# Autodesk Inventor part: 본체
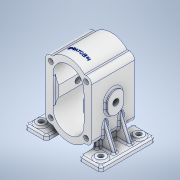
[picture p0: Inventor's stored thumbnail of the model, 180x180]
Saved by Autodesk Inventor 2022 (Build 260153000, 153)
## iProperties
Created: 2023-06
Part Number: 본체
Material: 알루미늄 6061
Document SubType Name: Modeling
Designer: PC-11
Density: 2.7 g/cm^3
Appearance: 알루미늄 - 평지
Author: PC-11
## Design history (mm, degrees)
sketch "스케치1"
  geometry: L1 (-42.5, 55)-(42.5, 55); L2 (42.5, 55)-(42.5, -55); L3 (42.5, -55)-(-42.5, -55); L4 (-42.5, -55)-(-42.5, 55); L5 (-42.5, 55)-(42.5, -55); L6 (42.5, 55)-(-42.5, -55); L7 (0, 0)-(0, -27.5); L8 (0, 0)-(0, 27.5); C1 r 40 at (0, -27.5); C2 r 40 at (0, 27.5); 4 further points
  constraints: 16 end point, 2 centre point, 2 coincident, 2 midpoint, 2 parallel, 2 vertical, 1 horizontal, 1 perpendicular
  dimensions: "d0" = 85 distance of L2.end L3.end; "d1" = 110 distance of L1.end L2.end; "d2" = 27.5 distance of L7.start L7.end; "d3" = 80 diameter of C1; "d4" = 27.5 distance of L7.start L8.end; "d5" = 80 diameter of C2
extrude "돌출1" new body sketch "스케치1" stored distance "d6" = 79; taper "d7" = 0 deg
fillet "모깎기1" dims "d8" = 10
sketch "스케치3"
  geometry: L1 (-32.5, -55)-(-29.047, -55) reference; L2 (29.047, -55)-(32.5, -55) reference; L3 (42.5, -45)-(42.5, 45) reference; L4 (32.5, 55)-(29.047, 55) reference; L5 (-29.047, 55)-(-32.5, 55) reference; L6 (-42.5, 45)-(-42.5, -45) reference; L7 (-22.5, 27.5)-(22.5, 27.5); L8 (22.5, 27.5)-(22.5, -27.5); L9 (22.5, -27.5)-(-22.5, -27.5); L10 (-22.5, -27.5)-(-22.5, 27.5); L11 (-22.5, 27.5)-(22.5, -27.5); L12 (22.5, 27.5)-(-22.5, -27.5); C1 r 28.5 at (0, -27.5); C2 r 28.5 at (0, 27.5); A1 r 10 centre (-32.5, -45) between (-42.5, -45) and (-32.5, -55) reference; A2 r 40 centre (0, -27.5) between (-29.047, -55) and (29.047, -55) reference; A3 r 10 centre (32.5, -45) between (32.5, -55) and (42.5, -45) reference; A4 r 10 centre (32.5, 45) between (42.5, 45) and (32.5, 55) reference; A5 r 40 centre (0, 27.5) between (29.047, 55) and (-29.047, 55) reference; A6 r 10 centre (-32.5, 45) between (-32.5, 55) and (-42.5, 45) reference; 7 further points
  constraints: 12 end point, 4 midpoint, 2 centre point, 2 coincident, 2 parallel, 1 horizontal, 1 perpendicular, 1 tangent, 1 vertical alignment
  dimensions: "d11" = 45 distance of L8.end L9.end; "d12" = 57 diameter of C1; "d13" = 57 diameter of C2
extrude "돌출2" cut sketch "스케치3" distance "d14" = 79; taper "d15" = 0 deg
sketch "스케치4"
  geometry: L1 (-22.5, -10.007)-(-22.5, 10.007) reference; L2 (22.5, 10.007)-(22.5, -10.007) reference; L3 (-32.5, -55)-(-29.047, -55) reference; L4 (29.047, -55)-(32.5, -55) reference; L5 (42.5, -45)-(42.5, 45) reference; L6 (32.5, 55)-(29.047, 55) reference; L7 (-29.047, 55)-(-32.5, 55) reference; L8 (-42.5, 45)-(-42.5, -45) reference; L9 (-28.5, 24)-(28.5, 24); L10 (28.5, 24)-(28.5, -24); L11 (28.5, -24)-(-28.5, -24); L12 (-28.5, -24)-(-28.5, 24); L13 (-28.5, 24)-(28.5, -24); L14 (28.5, 24)-(-28.5, -24); A1 r 28.5 centre (0, -27.5) between (-22.5, -10.007) and (22.5, -10.007) reference; A2 r 28.5 centre (0, 27.5) between (22.5, 10.007) and (-22.5, 10.007) reference; A3 r 10 centre (-32.5, -45) between (-42.5, -45) and (-32.5, -55) reference; A4 r 40 centre (0, -27.5) between (-29.047, -55) and (29.047, -55) reference; A5 r 10 centre (32.5, -45) between (32.5, -55) and (42.5, -45) reference; A6 r 10 centre (32.5, 45) between (42.5, 45) and (32.5, 55) reference; A7 r 40 centre (0, 27.5) between (29.047, 55) and (-29.047, 55) reference; A8 r 10 centre (-32.5, 45) between (-32.5, 55) and (-42.5, 45) reference; 5 further points
  constraints: 12 end point, 2 midpoint, 2 parallel, 1 horizontal, 1 perpendicular
  dimensions: "d16" = 57 distance of L10.end L11.end; "d17" = 48 distance of L9.end L10.end
extrude "돌출3" cut sketch "스케치4" distance "d18" = 4.5; taper "d19" = 0 deg
node "작업 평면2"
  node "작업 평면1"
sketch "스케치6"
  geometry: L1 (-30, -50)-(-70, -50); L2 (-70, -50)-(-70, 50); L3 (-70, 50)-(-30, 50); L4 (-30, 50)-(-30, -50); L5 (-42.5, 39.5)-(-42.5, -39.5) reference; L6 (0, 0)-(0, -39.5); L7 (-29.047, -39.5)-(29.047, -39.5) reference; L8 (70, 50)-(30, 50); L9 (70, -50)-(70, 50); L10 (30, 50)-(30, -50); L11 (30, -50)-(70, -50); 2 further points
  constraints: 18 end point, 4 symmetric about line, 3 midpoint, 2 parallel, 1 horizontal, 1 horizontal alignment, 1 perpendicular
  dimensions: "d21" = 40 distance of L2.end L3.end; "d22" = 100 distance of L1.end L2.end; "d23" = 70 distance from line of L2 L6.start
extrude "돌출4" join sketch "스케치6" distance "d24" = 9; taper "d25" = 0 deg
node "작업 평면3"
node "작업 평면4"
sketch "스케치7"
  geometry: L1 (22.5, -10.007)-(22.5, 10.007) reference; L2 (-22.5, 10.007)-(-22.5, -10.007) reference; L3 (-32.5, 55)-(-29.047, 55) reference; L4 (29.047, 55)-(32.5, 55) reference; L5 (42.5, 45)-(42.5, -45) reference; L6 (32.5, -55)-(29.047, -55) reference; L7 (-29.047, -55)-(-32.5, -55) reference; L8 (-42.5, -45)-(-42.5, 45) reference; L9 (30, -76.5)-(30, -67.5) reference; L10 (30, -67.5)-(70, -67.5) reference; L11 (70, -67.5)-(70, -76.5) reference; L12 (70, -76.5)-(30, -76.5) reference; L13 (-30, -67.5)-(-30, -76.5) reference; L14 (-30, -76.5)-(-70, -76.5) reference; L15 (-70, -76.5)-(-70, -67.5) reference; L16 (-70, -67.5)-(-30, -67.5) reference; L17 (70, -67.5)-(30, -67.5) reference; L18 (62, -67.5)-(42.5, -21.561); L19 (42.5, 45)-(42.5, -45) reference; L20 (62, -67.5)-(30, -67.5); L21 (30, -67.5)-(30, -55); L22 (32.5, -55)-(29.047, -55) reference; A1 r 28.5 centre (0, 27.5) between (22.5, 10.007) and (-22.5, 10.007) reference; A2 r 28.5 centre (0, -27.5) between (-22.5, -10.007) and (22.5, -10.007) reference; A3 r 10 centre (-32.5, 45) between (-32.5, 55) and (-42.5, 45) reference; A4 r 40 centre (0, 27.5) between (29.047, 55) and (-29.047, 55) reference; A5 r 10 centre (32.5, 45) between (42.5, 45) and (32.5, 55) reference; A6 r 10 centre (32.5, -45) between (32.5, -55) and (42.5, -45) reference; A7 r 40 centre (0, -27.5) between (-29.047, -55) and (29.047, -55) reference; A8 r 10 centre (-32.5, -45) between (-42.5, -45) and (-32.5, -55) reference; 4 further points
  constraints: 6 end point, 3 point on line, 1 perpendicular
  dimensions: "d28" = 8 distance of L10.end L18.start; "d29" = 23 deg angle of L11 L18
extrude "돌출5" join sketch "스케치7" stored distance "d30" = 7; taper "d31" = 0 deg
sketch "스케치10"
  geometry: L1 (30, 25)-(38, 25); L2 (38, 25)-(38, -25); L3 (38, -25)-(30, -25); L4 (30, -25)-(30, 25); L5 (30, 25)-(38, -25); L6 (38, 25)-(30, -25); L7 (30, 11)-(30, -11) reference; 3 further points
  constraints: 12 end point, 3 midpoint, 2 parallel, 1 collinear, 1 horizontal, 1 horizontal alignment, 1 perpendicular
  dimensions: "d36" = 8 distance of L2.end L3.end; "d37" = 50 distance of L1.end L2.end
extrude "돌출6" join sketch "스케치10" stored distance "d38" = 7; taper "d39" = 0 deg
fillet "모깎기2" dims "d40" = 5
sketch "스케치11"
  geometry: L1 (-38, -11)-(-38, 11) reference; L2 (-38, 11)-(-62, 11) reference; L3 (-62, 11)-(-62, 18) reference; L4 (-62, 18)-(-38, 18) reference; L5 (-38, 18)-(-38, 25) reference; L6 (-38, 25)-(-30, 25) reference; L7 (-30, 25)-(-30, -25) reference; L8 (-30, -25)-(-30, -45) reference; L9 (-35, -50)-(-65, -50) reference; L10 (-70, -45)-(-70, 45) reference; L11 (-65, 50)-(-35, 50) reference; L12 (-30, 45)-(-30, 25) reference; L13 (-62, -11)-(-38, -11) reference; L14 (-62, -18)-(-62, -11) reference; L15 (-38, -18)-(-62, -18) reference; L16 (-38, -25)-(-38, -18) reference; L17 (-30, -25)-(-38, -25) reference; L18 (38, 11)-(38, -11) reference; L19 (38, -11)-(62, -11) reference; L20 (62, -11)-(62, -18) reference; L21 (62, -18)-(38, -18) reference; L22 (38, -18)-(38, -25) reference; L23 (38, -25)-(30, -25) reference; L24 (30, -25)-(30, 25) reference; L25 (30, 25)-(30, 45) reference; L26 (35, 50)-(65, 50) reference; L27 (70, 45)-(70, -45) reference; L28 (65, -50)-(35, -50) reference; L29 (30, -45)-(30, -25) reference; L30 (62, 11)-(38, 11) reference; L31 (62, 18)-(62, 11) reference; L32 (38, 18)-(62, 18) reference; L33 (38, 25)-(38, 18) reference; L34 (30, 25)-(38, 25) reference; L35 (0, 39.5)-(0, -39.5) reference; C1 r 9 at (55, 35); C2 r 9 at (55, -35); C3 r 9 at (-55, 35); C4 r 9 at (-55, -35); A1 r 5 centre (-35, -45) between (-35, -50) and (-30, -45) reference; A2 r 5 centre (-65, -45) between (-70, -45) and (-65, -50) reference; A3 r 5 centre (-65, 45) between (-65, 50) and (-70, 45) reference; A4 r 5 centre (-35, 45) between (-30, 45) and (-35, 50) reference; A5 r 5 centre (35, 45) between (35, 50) and (30, 45) reference; A6 r 5 centre (65, 45) between (70, 45) and (65, 50) reference; A7 r 5 centre (65, -45) between (65, -50) and (70, -45) reference; A8 r 5 centre (35, -45) between (30, -45) and (35, -50) reference; 5 further points
  constraints: 4 centre point, 4 coincident, 2 horizontal alignment, 2 vertical alignment
  dimensions: "d41" = 110 distance of point (55, 35) point (-55, 35); "d42" = 70 distance of point (55, -35) point (55, 35); "d43" = 15 distance from line of L27 point (55, 35); "d44" = 35 vertical distance of point (0, 0) point (55, 35); "d45" = 18 diameter of C1; "d46" = 18 diameter of C2; "d47" = 18 diameter of C3; "d48" = 18 diameter of C4
extrude "돌출7" join sketch "스케치11" distance "d49" = 3; taper "d50" = 0 deg
sketch "스케치12"
  geometry: L1 (-93, 24)-(-93, 46) reference; L2 (-93, 46)-(-115.727, 46) reference; L3 (-115.727, 46)-(-115.727, 53) reference; L4 (-115.727, 53)-(-93, 53) reference; L5 (-93, 53)-(-93, 60) reference; L6 (-93, 60)-(-85, 60) reference; L7 (-85, 60)-(-85, 10) reference; L8 (-85, 10)-(-93, 10) reference; L9 (-93, 10)-(-93, 17) reference; L10 (-93, 17)-(-115.727, 17) reference; L11 (-115.727, 17)-(-115.727, 24) reference; L12 (-115.727, 24)-(-93, 24) reference; L13 (-17, 46)-(-17, 24) reference; L14 (-17, 24)-(5.727, 24) reference; L15 (5.727, 24)-(5.727, 17) reference; L16 (5.727, 17)-(-17, 17) reference; L17 (-17, 17)-(-17, 10) reference; L18 (-17, 10)-(-25, 10) reference; L19 (-25, 10)-(-25, 60) reference; L20 (-25, 60)-(-17, 60) reference; L21 (-17, 60)-(-17, 53) reference; L22 (-17, 53)-(5.727, 53) reference; L23 (5.727, 53)-(5.727, 46) reference; L24 (5.727, 46)-(-17, 46) reference; L25 (-70.199, 74.5)-(-39.801, 74.5) reference; L26 (-39.801, 74.5)-(-39.801, -4.5) reference; L27 (-39.801, -4.5)-(-70.199, -4.5) reference; L28 (-70.199, -4.5)-(-70.199, 74.5) reference; C1 r 9 at (-110, 0) reference; C2 r 9 at (0, 70) reference; C3 r 9 at (-110, 70) reference; C4 r 9 at (0, 0) reference; 5 further points
  constraints: 4 coincident
hole "구멍1" sketch "스케치12" at (-110, 0), (-110, 70), (0, 70), (0, 0) diameter "d51" = 9; stored, may be unused: countersink angle "d55" = 90 deg, drill point angle "d57" = 118 deg; dims "d52" = 0.8, "d53" = 4, "d54" = 2, "d56" = 1.3
sketch "스케치13"
  geometry: L1 (-32.5, -55)-(-29.047, -55) reference; L2 (29.047, -55)-(32.5, -55) reference; L3 (42.5, -45)-(42.5, 45) reference; L4 (32.5, 55)-(29.047, 55) reference; L5 (-29.047, 55)-(-32.5, 55) reference; L6 (-42.5, 45)-(-42.5, -45) reference; L7 (28.284, 24)-(28.5, 24) reference; L8 (28.5, 24)-(28.5, -24) reference; L9 (28.5, -24)-(28.284, -24) reference; L10 (-28.284, -24)-(-28.5, -24) reference; L11 (-28.5, -24)-(-28.5, 24) reference; L12 (-28.5, 24)-(-28.284, 24) reference; A1 r 10 centre (-32.5, -45) between (-42.5, -45) and (-32.5, -55) reference; A2 r 40 centre (0, -27.5) between (-29.047, -55) and (29.047, -55) reference; A3 r 10 centre (32.5, -45) between (32.5, -55) and (42.5, -45) reference; A4 r 10 centre (32.5, 45) between (42.5, 45) and (32.5, 55) reference; A5 r 40 centre (0, 27.5) between (29.047, 55) and (-29.047, 55) reference; A6 r 10 centre (-32.5, 45) between (-32.5, 55) and (-42.5, 45) reference; A7 r 28.5 centre (0, -27.5) between (-28.284, -24) and (28.284, -24) reference; A8 r 28.5 centre (0, 27.5) between (28.284, 24) and (-28.284, 24) reference; 5 further points
  constraints: 2 horizontal alignment, 2 vertical alignment
  dimensions: "d58" = 65 distance of point (32.5, 45) point (-32.5, 45); "d59" = 90 distance of point (-32.5, 45) point (-32.5, -45); "d60" = 45 vertical distance of point (-32.5, -45) point (0, 0); "d61" = 32.5 horizontal distance of point (0, 0) point (32.5, 45)
hole "구멍2" sketch "스케치13" at (32.5, 45), (-32.5, 45), (-32.5, -45), (32.5, -45) diameter "d62" = 9; stored, may be unused: countersink angle "d66" = 90 deg, drill point angle "d68" = 118 deg; dims "d63" = 6, "d64" = 4, "d65" = 2, "d67" = 8
sketch "스케치15"
  geometry: L1 (-39.5, 40)-(-39.5, 50); L2 (-54.5, 40)-(-54.5, 50); L3 (-24.5, 50)-(-24.5, 40); A1 r 15 centre (-39.5, 40) between (-54.5, 40) and (-24.5, 40); A2 r 15 centre (-39.5, 50) between (-24.5, 50) and (-54.5, 50); 1 further point
  constraints: 8 end point, 4 point on circle, 4 tangent, 2 centre point, 1 midpoint, 1 parallel, 1 vertical
  dimensions: "d69" = 30 distance between parallel lines of L3 L2; "d70" = 10 distance of L1.start L1.end
extrude "돌출8" join sketch "스케치15" distance "d71" = 5; taper "d72" = 0 deg
sketch "스케치16"
  geometry: 2 further points
  constraints: 1 coincident
hole "구멍3" sketch "스케치16" at (-39.5, 45) diameter "d73" = 10.5; stored, may be unused: countersink angle "d79" = 90 deg, drill point angle "d81" = 118 deg; dims "d74" = 11, "d75" = 0.62479, "d76" = 10.589, "d77" = 4, "d78" = 2, "d80" = 17.5
node "작업 평면5"
sketch "스케치17"
  geometry: 2 further points
  constraints: 1 vertical alignment, 1 other
  dimensions: "d82" = 20 distance of point (0, 20) point (0, 0)
feature "엠보싱1" sketch "스케치17" dims "d83" = 0.5, "d84" = 0
fillet "모깎기3" dims "d85" = 3
fillet "모깎기9" dims "d91" = 3
fillet "모깎기10" dims "d92" = 3
fillet "모깎기11" dims "d93" = 3
fillet "모깎기12" dims "d94" = 3
fillet "모깎기13" dims "d95" = 3
fillet "모깎기14" dims "d96" = 3
fillet "모깎기15" dims "d97" = 3
node "솔리드1"
mirror "미러1"
mirror "미러2"
mirror "미러3"
mirror "미러4"
mirror "미러5"
mirror "미러6"
node "투영된 루프1"
node "투영된 루프2"
node "투영된 루프3"
node "절단 모서리 투영1"
node "절단 모서리 투영2"
node "절단 모서리 투영3"
feature "A9D066F2-1C7D-4E18-AEED-F7BC21143FA4" dims "d51" = 9, "d52" = 0.8, "d53" = 4, "d54" = 2, "d55" = 90 deg, "d56" = 1.3, "d57" = 118 deg
other parameters: "d20" = -144, "d26" = 14.5, "d27" = -14.5
